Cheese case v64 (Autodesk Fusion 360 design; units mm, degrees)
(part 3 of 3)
sketch "Bottom supports" plane through (0, 6.234, 0) normal (0, 1, 0) x axis (-1, 0, 0)
  line L1 (-103.4724, -74.5035) -> (-103.4724, -52.9083)
  line L2 (-103.4724, -96.0987) -> (-103.4724, -74.5035)
  line L3 (-103.4724, -127.4117) -> (-103.4724, -117.6939)
  line L4 (-5.3988, -127.4117) -> (-103.4724, -127.4117)
  line L5 (-5.3988, -117.6939) -> (-5.3988, -127.4117)
  line L6 (-5.3988, -74.5035) -> (-5.3988, -96.0987)
  line L7 (-5.3988, -52.9083) -> (-5.3988, -74.5035)
  line L8 (-5.3988, -31.3131) -> (-5.3988, -52.9083)
  line L9 (-103.4724, 0) -> (-5.3988, 0)
  line L10 (-103.4724, -9.7178) -> (-103.4724, 0)
  line L11 (-103.4724, -52.9083) -> (-103.4724, -31.3131)
  line L12 (-103.4724, -74.5035) -> (-103.4724, -52.9083)
  line L13 (-5.3988, -117.6939) -> (-5.3988, -127.4117)
  line L14 (-5.3988, -74.5035) -> (-5.3988, -96.0987)
  line L15 (-5.3988, -127.4117) -> (-103.4724, -127.4117)
  line L16 (-103.4724, 0) -> (-5.3988, 0)
  line L17 (-5.3988, -31.3131) -> (-5.3988, -52.9083)
  line L18 (-95.5062, -36.0623) -> (-95.5062, -46.7938)
  line L19 (-24.5062, -79.7578) -> (-24.5062, -91.7938)
  line L20 (-96.0464, -37.7683) -> (-94.1581, -39.6567)
  line L21 (-95.5062, -38.3086) -> (-91.2635, -42.5512)
  line L22 (-97.2759, -81.5388) -> (-94.0474, -84.7673)
  line L23 (-95.5062, -83.3086) -> (-91.2635, -87.5512)
  line L24 (-95.5062, -79.2527) -> (-95.5062, -91.7938)
  line L25 (-24.5062, -83.1565) -> (-28.8222, -87.6259)
  line L26 (-28.7488, -42.5512) -> (-24.5062, -38.3086)
  line L27 (-5.3988, -52.9083) -> (-5.3988, -74.5035)
  line L28 (-20.2635, -42.5512) -> (-24.5062, -38.3086)
  line L29 (-24.5062, -29) -> (-24.5062, -46.7938)
  line L30 (-24.5062, -83.1565) -> (-20.1901, -87.6259)
  line L31 (-103.4724, -52.9083) -> (-103.4724, -31.3131)
  line L32 (-5.3988, 0) -> (-5.3988, -9.7178)
  line L33 (-103.4724, -96.0987) -> (-103.4724, -74.5035)
  line L34 (-103.4724, -127.4117) -> (-103.4724, -117.6939)
  line L35 (-103.4724, -9.7178) -> (-103.4724, 0)
  line L36 (-5.3988, 0) -> (-5.3988, -9.7178)
  circle C1 centre (-24.5062, -91.7938) radius 4
  circle C2 centre (-95.5062, -91.7938) radius 4
  circle C3 centre (-24.5062, -46.7938) radius 4
  circle C4 centre (-95.5062, -46.7938) radius 4
  arc A1 centre (-91.8396, -42.1107) radius 5.3988 clockwise from (-97.1264, -41.0168) to (-89.5091, -46.9805)
  arc A2 centre (-95.5062, -46.7938) radius 6 clockwise from (-97.1264, -41.0168) to (-89.5091, -46.9805)
  arc A3 centre (-98.0736, -52.9083) radius 5.3988 clockwise from (-92.7334, -52.1148) to (-103.4724, -52.9083)
  circle C5 centre (-98.0736, -74.5035) radius 5.3988
  arc A4 centre (-98.0736, -96.0987) radius 5.3988 clockwise from (-103.4724, -96.0987) to (-101.5046, -91.9303)
  arc A5 centre (-95.5062, -91.7938) radius 6 clockwise from (-95.3129, -97.7907) to (-101.5046, -91.9303)
  arc A6 centre (-90.9724, -109.5129) radius 12.5 clockwise from (-95.3129, -97.7907) to (-92.7954, -97.1466)
  arc A7 centre (-95.5062, -91.7938) radius 6 clockwise from (-92.7755, -97.1365) to (-92.7954, -97.1466)
  arc A8 centre (-98.0736, -96.0987) radius 5.3988 clockwise from (-92.7755, -97.1365) to (-92.7769, -97.1439)
  arc A9 centre (-90.9724, -109.5129) radius 12.5 clockwise from (-92.7769, -97.1439) to (-90.9264, -97.013)
  arc A10 centre (-85.6056, -96.0987) radius 5.3988 clockwise from (-90.9264, -97.013) to (-90.993, -95.7475)
  arc A11 centre (-95.5062, -91.7938) radius 6 clockwise from (-89.5367, -92.3982) to (-90.993, -95.7475)
  arc A12 centre (-85.6056, -96.0987) radius 5.3988 clockwise from (-89.5367, -92.3982) to (-82.3838, -100.4308)
  arc A13 centre (-90.9724, -109.5129) radius 12.5 clockwise from (-82.3838, -100.4308) to (-81.1395, -101.7952)
  arc A14 centre (-79.3716, -106.8963) radius 5.3988 clockwise from (-81.1395, -101.7952) to (-78.7785, -112.2624)
  arc A15 centre (-90.9724, -109.5129) radius 12.5 clockwise from (-78.7785, -112.2624) to (-80.4157, -116.2066)
  arc A16 centre (-85.6056, -117.6939) radius 5.3988 clockwise from (-80.4157, -116.2066) to (-89.0367, -121.8622)
  arc A17 centre (-90.9724, -109.5129) radius 12.5 clockwise from (-89.0367, -121.8622) to (-94.3056, -121.5603)
  arc A18 centre (-98.0736, -117.6939) radius 5.3988 clockwise from (-94.3056, -121.5603) to (-103.4724, -117.6939)
  arc A19 centre (-10.7976, -117.6939) radius 5.3988 clockwise from (-5.3988, -117.6939) to (-14.5656, -121.5603)
  arc A20 centre (-17.8988, -109.5129) radius 12.5 clockwise from (-14.5656, -121.5603) to (-19.8345, -121.8622)
  arc A21 centre (-23.2656, -117.6939) radius 5.3988 clockwise from (-19.8345, -121.8622) to (-28.4555, -116.2066)
  arc A22 centre (-17.8988, -109.5129) radius 12.5 clockwise from (-28.4555, -116.2066) to (-30.0927, -112.2624)
  arc A23 centre (-29.4996, -106.8963) radius 5.3988 clockwise from (-30.0927, -112.2624) to (-27.7317, -101.7952)
  arc A24 centre (-17.8988, -109.5129) radius 12.5 clockwise from (-27.7317, -101.7952) to (-26.4874, -100.4308)
  arc A25 centre (-23.2656, -96.0987) radius 5.3988 clockwise from (-26.4874, -100.4308) to (-28.6644, -96.1193)
  arc A26 centre (-24.5062, -91.7938) radius 6 clockwise from (-18.6838, -93.2431) to (-28.6644, -96.1193)
  arc A27 centre (-23.2656, -96.0987) radius 5.3988 clockwise from (-18.6838, -93.2431) to (-17.9448, -97.013)
  arc A28 centre (-17.8988, -109.5129) radius 12.5 clockwise from (-17.9448, -97.013) to (-16.0943, -97.1439)
  arc A29 centre (-10.7976, -96.0987) radius 5.3988 clockwise from (-16.0943, -97.1439) to (-5.3988, -96.0987)
  circle C6 centre (-10.7976, -74.5035) radius 5.3988
  circle C7 centre (-10.7976, -52.9083) radius 5.3988
  arc A30 centre (-10.7976, -31.3131) radius 5.3988 clockwise from (-5.3988, -31.3131) to (-16.0943, -30.2679)
  arc A31 centre (-17.8988, -17.8988) radius 12.5 clockwise from (-16.0943, -30.2679) to (-17.9448, -30.3987)
  arc A32 centre (-23.2656, -31.3131) radius 5.3988 clockwise from (-17.9448, -30.3987) to (-26.4874, -26.981)
  arc A33 centre (-17.8988, -17.8988) radius 12.5 clockwise from (-26.4874, -26.981) to (-27.7317, -25.6166)
  arc A34 centre (-29.4996, -20.5154) radius 5.3988 clockwise from (-27.7317, -25.6166) to (-30.0927, -15.1493)
  arc A35 centre (-17.8988, -17.8988) radius 12.5 clockwise from (-30.0927, -15.1493) to (-28.4555, -11.2051)
  arc A36 centre (-23.2656, -9.7178) radius 5.3988 clockwise from (-28.4555, -11.2051) to (-19.8345, -5.5496)
  arc A37 centre (-17.8988, -17.8988) radius 12.5 clockwise from (-19.8345, -5.5496) to (-14.5656, -5.8514)
  arc A38 centre (-10.7976, -9.7178) radius 5.3988 clockwise from (-14.5656, -5.8514) to (-5.3988, -9.7178)
  arc A39 centre (-98.0736, -9.7178) radius 5.3988 clockwise from (-103.4724, -9.7178) to (-94.3056, -5.8514)
  arc A40 centre (-90.9724, -17.8988) radius 12.5 clockwise from (-94.3056, -5.8514) to (-89.0367, -5.5496)
  arc A41 centre (-85.6056, -9.7178) radius 5.3988 clockwise from (-89.0367, -5.5496) to (-80.4157, -11.2051)
  arc A42 centre (-90.9724, -17.8988) radius 12.5 clockwise from (-80.4157, -11.2051) to (-78.7785, -15.1493)
  arc A43 centre (-79.3716, -20.5154) radius 5.3988 clockwise from (-78.7785, -15.1493) to (-81.1395, -25.6166)
  arc A44 centre (-90.9724, -17.8988) radius 12.5 clockwise from (-81.1395, -25.6166) to (-82.3838, -26.981)
  arc A45 centre (-85.6056, -31.3131) radius 5.3988 clockwise from (-82.3838, -26.981) to (-90.9264, -30.3987)
  arc A46 centre (-90.9724, -17.8988) radius 12.5 clockwise from (-90.9264, -30.3987) to (-92.7769, -30.2679)
  arc A47 centre (-98.0736, -31.3131) radius 5.3988 clockwise from (-92.7769, -30.2679) to (-103.4724, -31.3131)
  arc A48 centre (-98.0736, -52.9083) radius 5.3988 clockwise from (-103.4724, -52.9083) to (-101.2464, -48.5401)
  arc A49 centre (-95.5062, -46.7938) radius 6 clockwise from (-92.7334, -52.1148) to (-101.2464, -48.5401)
  circle C8 centre (-41.9676, -63.7059) radius 5.3988
  circle C9 centre (-41.9676, -42.1107) radius 5.3988
  circle C10 centre (-35.7336, -52.9083) radius 5.3988
  circle C11 centre (-79.3716, -63.7059) radius 5.3988
  circle C12 centre (-79.3716, -85.3011) radius 5.3988
  circle C13 centre (-35.7336, -96.0987) radius 5.3988
  circle C14 centre (-35.7336, -117.6939) radius 5.3988
  circle C15 centre (-41.9676, -20.5154) radius 5.3988
  circle C16 centre (-41.9676, -85.3011) radius 5.3988
  circle C17 centre (-17.0316, -63.7059) radius 5.3988
  circle C18 centre (-29.4996, -63.7059) radius 5.3988
  circle C19 centre (-48.2016, -31.3131) radius 5.3988
  circle C20 centre (-35.7336, -74.5035) radius 5.3988
  circle C21 centre (-35.7336, -9.7178) radius 5.3988
  circle C22 centre (-35.7336, -31.3131) radius 5.3988
  circle C23 centre (-48.2016, -9.7178) radius 5.3988
  arc A50 centre (-17.0316, -85.3011) radius 5.3988 clockwise from (-22.3564, -86.1922) to (-18.6589, -90.4488)
  arc A51 centre (-24.5062, -91.7938) radius 6 clockwise from (-22.3564, -86.1922) to (-18.6589, -90.4488)
  circle C24 centre (-66.9036, -106.8963) radius 5.3988
  circle C25 centre (-73.1376, -31.3131) radius 5.3988
  circle C26 centre (-73.1376, -96.0987) radius 5.3988
  circle C27 centre (-66.9036, -85.3011) radius 5.3988
  circle C28 centre (-66.9036, -42.1107) radius 5.3988
  circle C29 centre (-66.9036, -63.7059) radius 5.3988
  circle C30 centre (-66.9036, -20.5154) radius 5.3988
  circle C31 centre (-60.6696, -117.6939) radius 5.3988
  circle C32 centre (-60.6696, -31.3131) radius 5.3988
  circle C33 centre (-60.6696, -96.0987) radius 5.3988
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  point P240 (-24.5062, -91.7938)
  point P265 (-24.5062, -91.7938)
  point P243 (-24.5062, -83.1565)
  point P245 (-24.5062, -83.1565)
  point P260 (-95.5062, -91.7938)
  point P266 (-95.5062, -91.7938)
  point P262 (-95.5062, -46.7938)
  point P268 (-95.5062, -46.7938)
  point P221 (-95.5062, -83.3086)
  point P222 (-94.0474, -84.7673)
  point P227 (-95.5062, -38.3086)
  point P168 (-94.1581, -39.6567)
  point P170 (-24.5062, -46.7938)
  point P267 (-24.5062, -46.7938)
  point P172 (-24.5062, -38.3086)
  coincident P240 P265
  vertical L19
  coincident P243 L19
  coincident P245 L19
  coincident P260 P266
  vertical L24
  coincident P262 P268
  parallel L18 L24
  coincident P221 L24
  coincident P222 L23
  parallel L22 L23
  coincident P227 L18
  coincident P168 L21
  parallel L20 L21
  coincident P170 P267
  vertical L29
  coincident P172 L29
  dimension "d613" angle L19 L25 = 44
  dimension "d614" angle L19 L30 = 44
  dimension "d615" angle L23 L24 = 45
  dimension "d616" angle L18 L21 = 45
  dimension "d617" angle L26 L29 = 45
extrude "Extrude49" add sketch "Bottom supports" no distance stored
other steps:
create_component "CreateComponent4"
create_component "CreateComponent1"
create_component "CreateComponent1"
create_component "CreateComponent2"
create_component "CreateComponent1"
create_component "CreateComponent3"
create_component "CreateComponent1"
create_component "CreateComponent4"
create_component "CreateComponent1"
create_component "CreateComponent5"
create_component "CreateComponent1"
create_component "CreateComponent6"
create_component "CreateComponent1"
create_component "CreateComponent7"
create_component "CreateComponent5"
create_component "CreateComponent6"
create_component "CreateComponent7"
named bodies: "Boden", "Vorne", "Links", "Deckel", "Rechts", "Back", "Holder"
